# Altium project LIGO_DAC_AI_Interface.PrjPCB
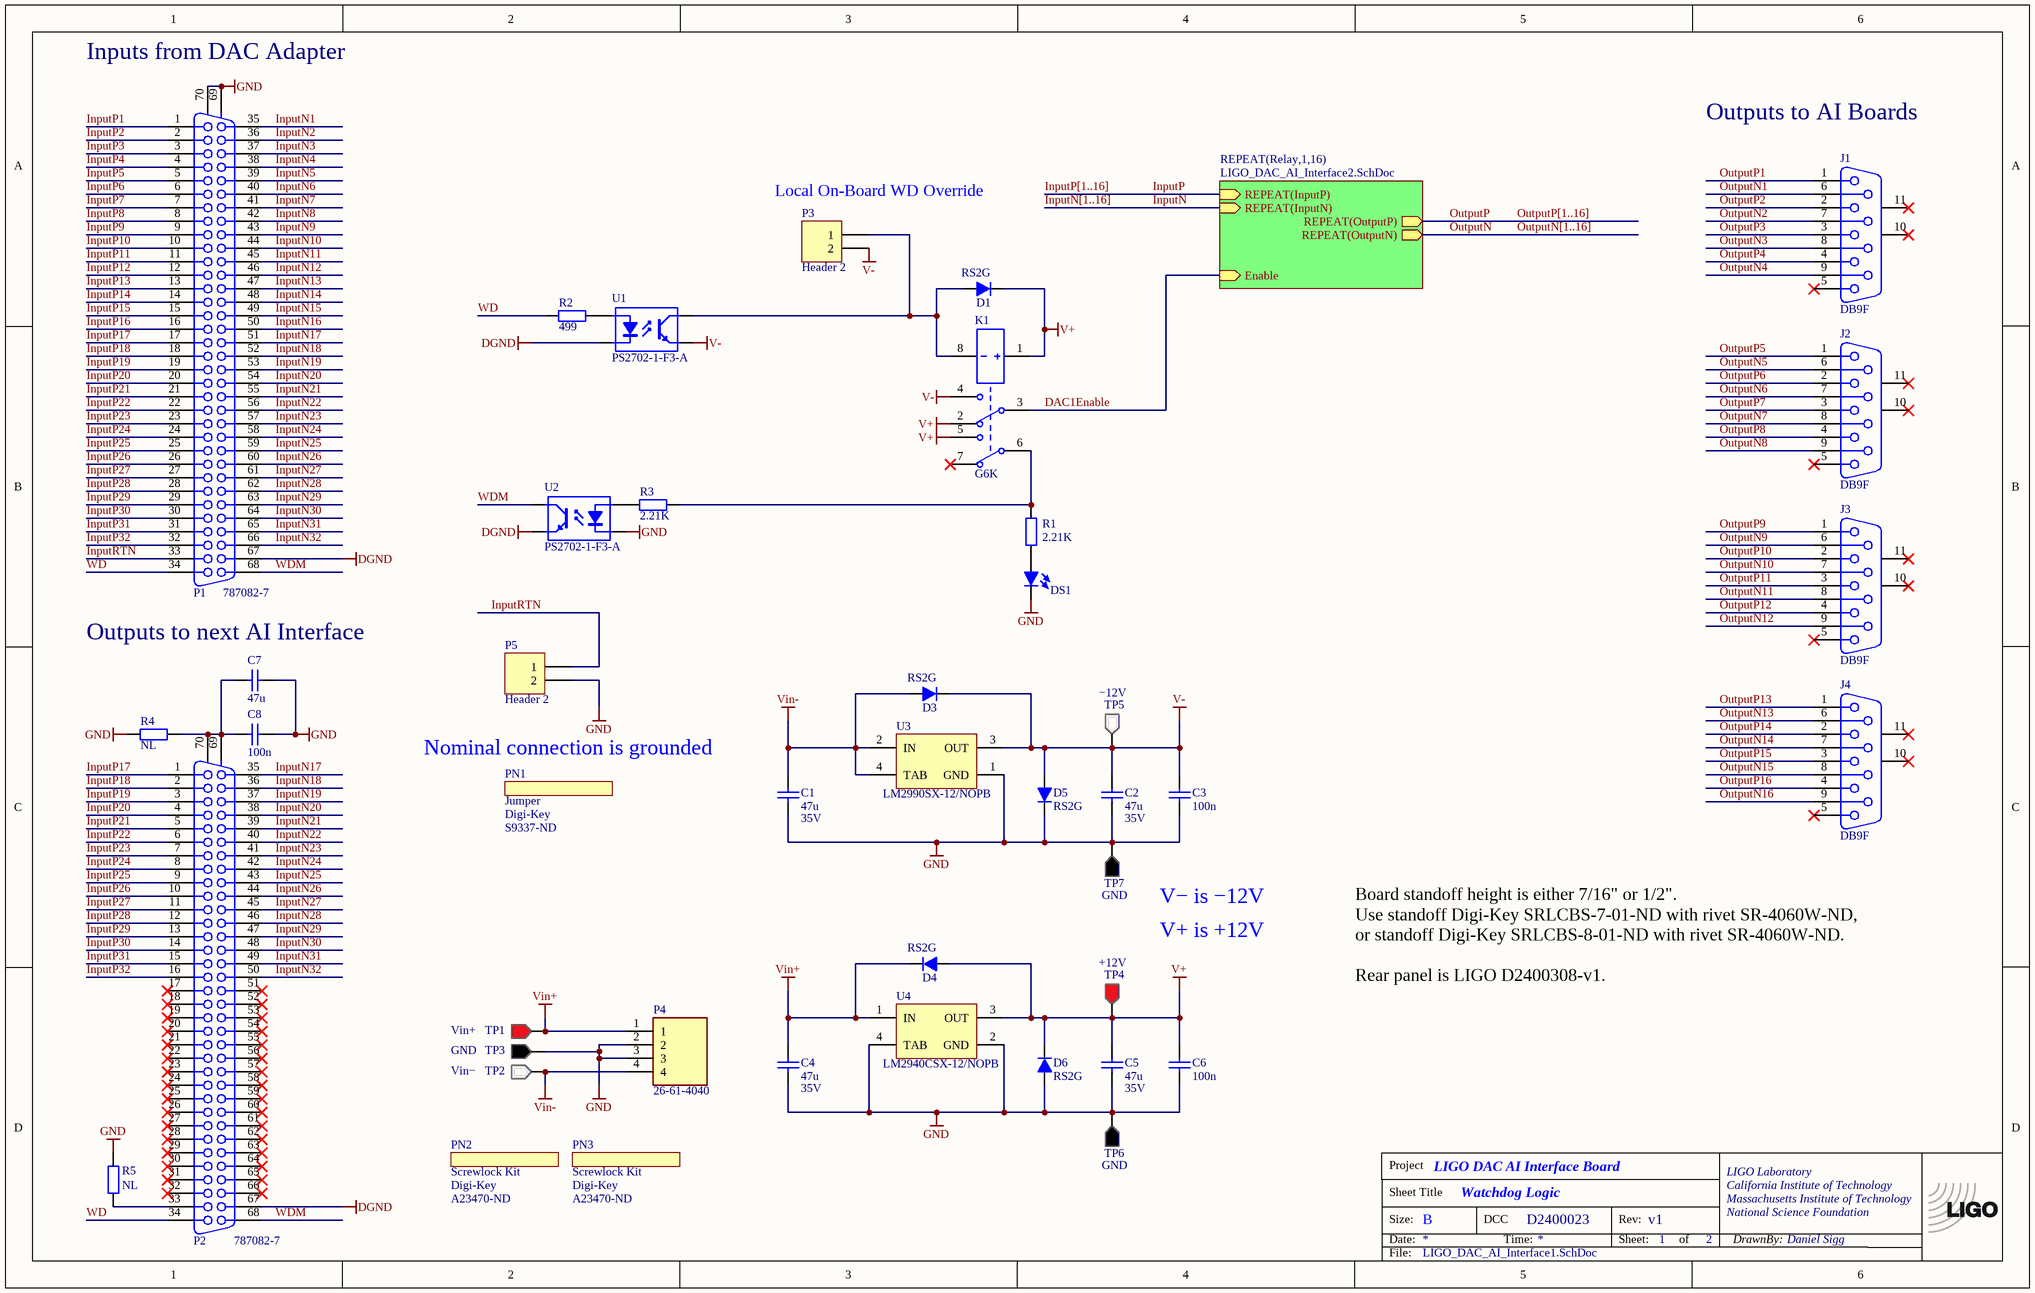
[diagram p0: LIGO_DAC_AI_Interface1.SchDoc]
Rev: v1; Project: LIGO DAC AI Interface Board; Eng: Daniel Sigg; DCC: D2400023
2 sheets, 92 parts. Net scope: hierarchical (ports join the sheet entries above them; power ports are global).
Board file: LIGO_DAC_AI_Interface.PcbDoc
Sheets:
  LIGO_DAC_AI_Interface1.SchDoc
    Relay1 = LIGO_DAC_AI_Interface2.SchDoc
    Relay2 = LIGO_DAC_AI_Interface2.SchDoc
    Relay3 = LIGO_DAC_AI_Interface2.SchDoc
    Relay4 = LIGO_DAC_AI_Interface2.SchDoc
    Relay5 = LIGO_DAC_AI_Interface2.SchDoc
    Relay6 = LIGO_DAC_AI_Interface2.SchDoc
    Relay7 = LIGO_DAC_AI_Interface2.SchDoc
    Relay8 = LIGO_DAC_AI_Interface2.SchDoc
    Relay9 = LIGO_DAC_AI_Interface2.SchDoc
    Relay10 = LIGO_DAC_AI_Interface2.SchDoc
    Relay11 = LIGO_DAC_AI_Interface2.SchDoc
    Relay12 = LIGO_DAC_AI_Interface2.SchDoc
    Relay13 = LIGO_DAC_AI_Interface2.SchDoc
    Relay14 = LIGO_DAC_AI_Interface2.SchDoc
    Relay15 = LIGO_DAC_AI_Interface2.SchDoc
    Relay16 = LIGO_DAC_AI_Interface2.SchDoc

## Sheet LIGO_DAC_AI_Interface1.SchDoc: Watchdog Logic
size B; Engineer: Daniel Sigg; DocumentNumber: D2400023; Revision: v1; SheetNumber: 1; SheetTotal: 2; PageSetup: Record=PageOptions¦CenterHorizontal=True¦CenterVertical=True¦PrintScale=1.12¦XCorrection=1.00¦YCorrection=1.00¦PrintKind=0¦BorderSize=5000000¦LeftOffset=0¦BottomOffset=0¦Orientation=2¦PaperLength=1000¦PaperWidth=1000¦Scale=100¦PaperSource=15¦PrintQuality=600¦MediaType=1¦DitherType=10¦PaperKind=Tabloid¦PrintScaleMode=1; SHEETSIZE: B

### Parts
*?  TitleBlock  (value not drawn)  (graphical)
C1  Voltage Rating: 35V  [CC5650-2220]  (hidden comment: 47u)
C2  Voltage Rating: 35V  [CC5650-2220]  (hidden comment: 47u)
C3  100n  [CC2013-0805]
C4  Voltage Rating: 35V  [CC5650-2220]  (hidden comment: 47u)
C5  Voltage Rating: 35V  [CC5650-2220]  (hidden comment: 47u)
C6  100n  [CC2013-0805]
C7  47u  [CC5650-2220]
C8  100n  [CC2013-0805]
D1  RS2G  [DO-SMB]
D3  RS2G  [DO-SMB]
D4  RS2G  [DO-SMB]
D5  RS2G  [DO-SMB]
D6  RS2G  [DO-SMB]
DS1  LED  [LED-1]  (value not drawn)
J1  DB9F  [DB9F-ST]
J2  DB9F  [DB9F-ST]
J3  DB9F  [DB9F-ST]
J4  DB9F  [DB9F-ST]
K1  G6K  [RELAY_G6K-2F]
P1  787082-7  [787082-7]
P2  787082-7  [787082-7]
P3  Header 2  [TSW-102-XX-YY-S]
P4  26-61-4040  [HDRV4W155P0X396_1X4_1570X1001X1536P]
P5  Header 2  [TSW-102-XX-YY-S]
PN1  Jumper  Part Number: S9337-ND  Distributor: Digi-Key  (mechanical)
PN2  Screwlock Kit  Part Number: A23470-ND  Distributor: Digi-Key  (mechanical)
PN3  Screwlock Kit  Part Number: A23470-ND  Distributor: Digi-Key  (mechanical)
R1  2.21K  [CR2012-0805]
R2  499  [CR2012-0805]
R3  2.21K  [CR2012-0805]
R4  NL  [CR2012-0805]
R5  NL  [CR2012-0805]
TP1  Vin+  [TP1-RED]
TP2  Vin−  [TP1-WHT]
TP3  GND  [TP1-BLK]
TP4  +12V  [TP1-RED]
TP5  −12V  [TP1-WHT]
TP6  GND  [TP1-BLK]
TP7  GND  [TP1-BLK]
U1  PS2702-1-F3-A  [PS2701A-1]
U2  PS2702-1-F3-A  [PS2701A-1]
U3  LM2990SX-12/NOPB  [KTT0003B_N]
U4  LM2940CSX-12/NOPB  [KTT0003B_N]

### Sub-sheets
REPEAT(Relay,1,16) = LIGO_DAC_AI_Interface2.SchDoc: REPEAT(InputP) (in), REPEAT(InputN) (in), REPEAT(OutputP) (out), REPEAT(OutputN) (out), Enable (in)

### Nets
DGND: P1.67 P2.67 U1.2(K) U2.3(E)
GND: C1.1 C2.1 C3.1 C4.1 C5.1 C6.1 C7.1 C8.1 D5.2(K) D6.1(A) DS1.1(K) P1.69(MH1) P1.70(MH2) P4.2 P4.3 P5.2 R4.2 R5.2 TP3.1 TP6.1 TP7.1 U2.2(K) U3.1(GND) U4.2(GND) U4.4(TAB)
V+: C5.2 C6.2 D1.2(K) D4.1(A) D6.2(K) K1.1(COIL1) K1.2(2NC) K1.5(1NO) TP4.1 U4.3(OUT)
V-: C2.2 C3.2 D3.2(K) D5.1(A) K1.4(2NO) P3.2 TP5.1 U1.3(E) U3.3(OUT)
Vin+: C4.2 D4.2(K) P4.1 TP1.1 U4.1(IN)
Vin-: C1.2 D3.1(A) P4.4 TP2.1 U3.2(IN) U3.4(TAB)
DAC1Enable: K1.3(2COM) ; sheet REPEAT(Relay,1,16)/Enable
InputN1: P1.35
InputN2: P1.36
InputN3: P1.37
InputN4: P1.38
InputN5: P1.39
InputN6: P1.40
InputN7: P1.41
InputN8: P1.42
InputN9: P1.43
InputN10: P1.44
InputN11: P1.45
InputN12: P1.46
InputN13: P1.47
InputN14: P1.48
InputN15: P1.49
InputN16: P1.50
InputN17: P1.51 P2.35
InputN18: P1.52 P2.36
InputN19: P1.53 P2.37
InputN20: P1.54 P2.38
InputN21: P1.55 P2.39
InputN22: P1.56 P2.40
InputN23: P1.57 P2.41
InputN24: P1.58 P2.42
InputN25: P1.59 P2.43
InputN26: P1.60 P2.44
InputN27: P1.61 P2.45
InputN28: P1.62 P2.46
InputN29: P1.63 P2.47
InputN30: P1.64 P2.48
InputN31: P1.65 P2.49
InputN32: P1.66 P2.50
InputP1: P1.1
InputP2: P1.2
InputP3: P1.3
InputP4: P1.4
InputP5: P1.5
InputP6: P1.6
InputP7: P1.7
InputP8: P1.8
InputP9: P1.9
InputP10: P1.10
InputP11: P1.11
InputP12: P1.12
InputP13: P1.13
InputP14: P1.14
InputP15: P1.15
InputP16: P1.16
InputP17: P1.17 P2.1
InputP18: P1.18 P2.2
InputP19: P1.19 P2.3
InputP20: P1.20 P2.4
InputP21: P1.21 P2.5
InputP22: P1.22 P2.6
InputP23: P1.23 P2.7
InputP24: P1.24 P2.8
InputP25: P1.25 P2.9
InputP26: P1.26 P2.10
InputP27: P1.27 P2.11
InputP28: P1.28 P2.12
InputP29: P1.29 P2.13
InputP30: P1.30 P2.14
InputP31: P1.31 P2.15
InputP32: P1.32 P2.16
InputRTN: P1.33 P5.1
OutputN1: J1.6
OutputN2: J1.7
OutputN3: J1.8
OutputN4: J1.9
OutputN5: J2.6
OutputN6: J2.7
OutputN7: J2.8
OutputN8: J2.9
OutputN9: J3.6
OutputN10: J3.7
OutputN11: J3.8
OutputN12: J3.9
OutputN13: J4.6
OutputN14: J4.7
OutputN15: J4.8
OutputN16: J4.9
OutputP1: J1.1
OutputP2: J1.2
OutputP3: J1.3
OutputP4: J1.4
OutputP5: J2.1
OutputP6: J2.2
OutputP7: J2.3
OutputP8: J2.4
OutputP9: J3.1
OutputP10: J3.2
OutputP11: J3.3
OutputP12: J3.4
OutputP13: J4.1
OutputP14: J4.2
OutputP15: J4.3
OutputP16: J4.4
WD: P1.34 P2.34 R2.1
WDM: P1.68 P2.68 U2.4(C)
NetC7_2: C7.2 C8.2 P2.69(MH1) P2.70(MH2) R4.1
NetD1_1: D1.1(A) K1.8(COIL2) P3.1 U1.4(C)
NetDS1_2: DS1.2(A) R1.1
NetK1_6: K1.6(1COM) R1.2 R3.2
NetP2_33: P2.33 R5.1
NetR2_2: R2.2 U1.1(A)
NetR3_1: R3.1 U2.1(A)

Not connected (* = marked no-connect by the designer): J1 5* 10(MH1)* 11(MH2)*; J2 5* 10(MH1)* 11(MH2)*; J3 5* 10(MH1)* 11(MH2)*; J4 5* 10(MH1)* 11(MH2)*; K1 7(1NC)*; P2 17* 18* 19* 20* 21* 22* 23* 24* 25* 26* 27* 28* 29* 30* 31* 32* 51* 52* 53* 54* 55* 56* 57* 58* 59* 60* 61* 62* 63* 64* 65* 66*

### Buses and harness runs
bus InputN[1..16]
bus InputP[1..16]
bus OutputN[1..16]
bus OutputP[1..16]

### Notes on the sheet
- (near P1) Inputs from DAC Adapter
- Outputs to AI Boards
- (near P3) Local On-Board WD Override
- Outputs to next AI Interface
- (near PN1) Nominal connection is grounded
- V− is −12V
- V+ is +12V
- Board standoff height is either 7/16" or 1/2".
  Use standoff Digi-Key SRLCBS-7-01-ND with rivet SR-4060W-ND,
  or standoff Digi-Key SRLCBS-8-01-ND with rivet SR-4060W-ND.
  Rear panel is LIGO D2400308-v1.

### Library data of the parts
C1 C2 C4 C5 = ChipCap: Capacitor, surface mount; Part Number: 445-C5750X7R1V476M230KCCT-ND; Tolerance: 10%
C3 C6 C8 = ChipCap: Capacitor, surface mount; Part Number: 311-1140-1-ND; Tolerance: 10%
C7 = ChipCap: Capacitor, surface mount; Part Number: 445-C5750X7R1V476M230KCCT-ND; Tolerance: 10%; Voltage Rating: 35V
D1 D3-D6 = DIODE: Single diode; Part Number: RS2G-E3/52TGICT-ND; Voltage Rating: 400V
DS1 = LED: Panel mount LED; Part Number: 67-1304-ND
J1-J4 = DB9F: Receptacle Assembly, 9 Position, Right Angle, .318 Series; Part Number: A34072-ND
K1 = Relay_DPDT_GK: Dual-pole dual-throw relay; Part Number: Z114CT-ND; Coil Voltage: 24V; Current Rating: 2A
P1 P2 = 787082-7: Receptacle Assembly, Shielded, Right Angle, AMPLIMITE; Part Number: A31814-ND
P3 P5 = Header 2: Header, 2-Pin; Part Number: SAM10844-ND
P4 = 26-61-4040: Connector; Manufacturer_Name: Molex; Part Number: WM5226-ND
PN1 = Partlist
PN2 PN3 = Partlist: Jackscrew Socket, Slotted For AMPLIMITE Series: 786585-2
R1 R3 = ChipRes1: Resistor, surface mount; Part Number: 311-2.21KCRCT-ND; Tolerance: 1%
R2 = ChipRes1: Resistor, surface mount; Part Number: 311-499CRCT-ND; Tolerance: 1%
R4 R5 = ChipRes1: Resistor, surface mount; Tolerance: 1%
TP1 TP4 = TP_POSITIVE: Testpoint, red; Part Number: 5005K-ND
TP2 TP5 = TP_NEGATIVE: Testpoint, white; Part Number: 5007K-ND
TP3 TP6 TP7 = TP_GND: Testpoint, black; Part Number: 5006K-ND
U1 U2 = PS2701A: High Isolation Voltage SOP Photocoupler; Part Number: 559-1027-1-ND
U3 = LM2990SX-12: Negative Low Dropout Regulator, 3-pin TO-263; Part Number: LM2990SX-12/NOPBCT-ND
U4 = LM2940CS-12/NOPB: 1A Low Dropout Regulator, 3-pin TO-263, Pb-Free; Part Number: LM2940CSX-12/NOPBCT-ND

## Sheet LIGO_DAC_AI_Interface2.SchDoc: Signal Relays
size A; Engineer: Daniel Sigg; DocumentNumber: D2400023; Revision: v1; SheetNumber: 2; SheetTotal: 2; SHEETSIZE: A
Used 16 times, as channels Relay1, Relay2, Relay3, Relay4, Relay5, Relay6, Relay7, Relay8, Relay9, Relay10, Relay11, Relay12, Relay13, Relay14, Relay15, Relay16. Parts and nets are listed once, with the designators drawn on the sheet.
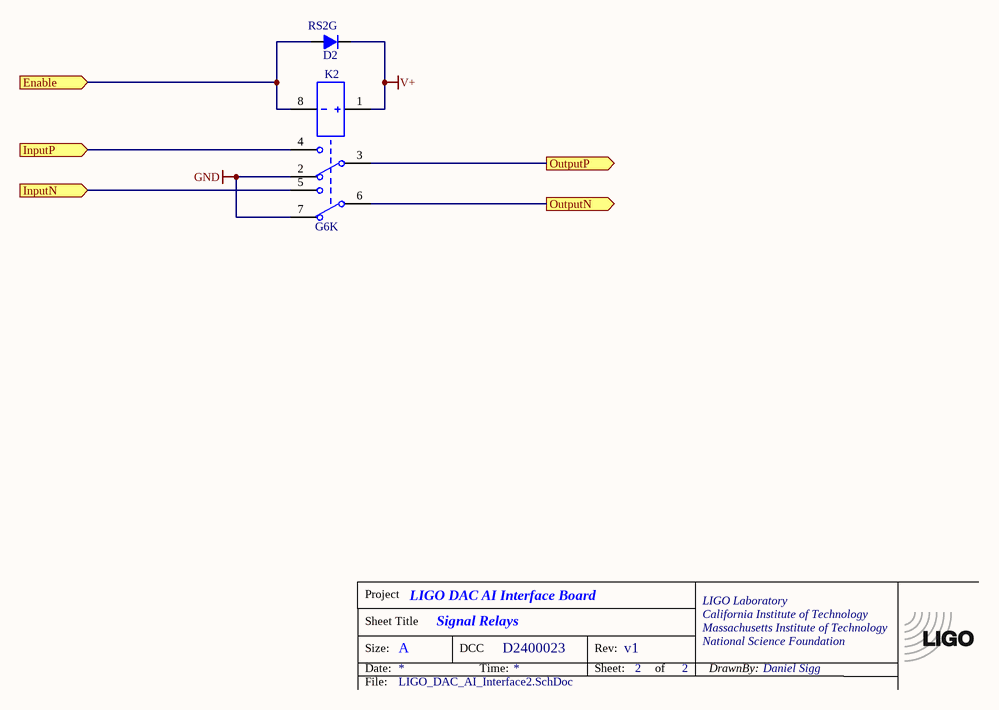
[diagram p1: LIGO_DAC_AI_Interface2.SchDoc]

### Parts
*?  TitleBlock  (value not drawn)  (graphical)
D2  RS2G  [DO-SMB]
K2  G6K  [RELAY_G6K-2F]

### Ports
Enable (in), InputN (in), InputP (in), OutputN (out), OutputP (out)

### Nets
GND: K2.2(2NC) K2.7(1NC)
V+: D2.2(K) K2.1(COIL1)
Enable: D2.1(A) K2.8(COIL2) ; port Enable
InputN: K2.5(1NO) ; port InputN
InputP: K2.4(2NO) ; port InputP
OutputN: K2.6(1COM) ; port OutputN
OutputP: K2.3(2COM) ; port OutputP

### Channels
Relay1: designators end in A; ports Enable=DAC1Enable InputN=InputN1 InputP=InputP1 OutputN=OutputN1 OutputP=OutputP1
Relay2: designators end in B; ports Enable=DAC1Enable InputN=InputN2 InputP=InputP2 OutputN=OutputN2 OutputP=OutputP2
Relay3: designators end in C; ports Enable=DAC1Enable InputN=InputN3 InputP=InputP3 OutputN=OutputN3 OutputP=OutputP3
Relay4: designators end in D; ports Enable=DAC1Enable InputN=InputN4 InputP=InputP4 OutputN=OutputN4 OutputP=OutputP4
Relay5: designators end in E; ports Enable=DAC1Enable InputN=InputN5 InputP=InputP5 OutputN=OutputN5 OutputP=OutputP5
Relay6: designators end in F; ports Enable=DAC1Enable InputN=InputN6 InputP=InputP6 OutputN=OutputN6 OutputP=OutputP6
Relay7: designators end in G; ports Enable=DAC1Enable InputN=InputN7 InputP=InputP7 OutputN=OutputN7 OutputP=OutputP7
Relay8: designators end in H; ports Enable=DAC1Enable InputN=InputN8 InputP=InputP8 OutputN=OutputN8 OutputP=OutputP8
Relay9: designators end in I; ports Enable=DAC1Enable InputN=InputN9 InputP=InputP9 OutputN=OutputN9 OutputP=OutputP9
Relay10: designators end in J; ports Enable=DAC1Enable InputN=InputN10 InputP=InputP10 OutputN=OutputN10 OutputP=OutputP10
Relay11: designators end in K; ports Enable=DAC1Enable InputN=InputN11 InputP=InputP11 OutputN=OutputN11 OutputP=OutputP11
Relay12: designators end in L; ports Enable=DAC1Enable InputN=InputN12 InputP=InputP12 OutputN=OutputN12 OutputP=OutputP12
Relay13: designators end in M; ports Enable=DAC1Enable InputN=InputN13 InputP=InputP13 OutputN=OutputN13 OutputP=OutputP13
Relay14: designators end in N; ports Enable=DAC1Enable InputN=InputN14 InputP=InputP14 OutputN=OutputN14 OutputP=OutputP14
Relay15: designators end in O; ports Enable=DAC1Enable InputN=InputN15 InputP=InputP15 OutputN=OutputN15 OutputP=OutputP15
Relay16: designators end in P; ports Enable=DAC1Enable InputN=InputN16 InputP=InputP16 OutputN=OutputN16 OutputP=OutputP16

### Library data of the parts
D2 = DIODE: as D1 on sheet LIGO_DAC_AI_Interface1
K2 = Relay_DPDT_GK: as K1 on sheet LIGO_DAC_AI_Interface1

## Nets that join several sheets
GND: LIGO_DAC_AI_Interface1 (25 pins), Relay1 (K2A.2 K2A.7), Relay2 (K2B.2 K2B.7), Relay3 (K2C.2 K2C.7), Relay4 (K2D.2 K2D.7), Relay5 (K2E.2 K2E.7), Relay6 (K2F.2 K2F.7), Relay7 (K2G.2 K2G.7), Relay8 (K2H.2 K2H.7), Relay9 (K2I.2 K2I.7), Relay10 (K2J.2 K2J.7), Relay11 (K2K.2 K2K.7), Relay12 (K2L.2 K2L.7), Relay13 (K2M.2 K2M.7), Relay14 (K2N.2 K2N.7), Relay15 (K2O.2 K2O.7), Relay16 (K2P.2 K2P.7)
V+: LIGO_DAC_AI_Interface1 (10 pins), Relay1 (D2A.2 K2A.1), Relay2 (D2B.2 K2B.1), Relay3 (D2C.2 K2C.1), Relay4 (D2D.2 K2D.1), Relay5 (D2E.2 K2E.1), Relay6 (D2F.2 K2F.1), Relay7 (D2G.2 K2G.1), Relay8 (D2H.2 K2H.1), Relay9 (D2I.2 K2I.1), Relay10 (D2J.2 K2J.1), Relay11 (D2K.2 K2K.1), Relay12 (D2L.2 K2L.1), Relay13 (D2M.2 K2M.1), Relay14 (D2N.2 K2N.1), Relay15 (D2O.2 K2O.1), Relay16 (D2P.2 K2P.1)
DAC1Enable: LIGO_DAC_AI_Interface1 (K1.3), Relay1 (D2A.1 K2A.8), Relay2 (D2B.1 K2B.8), Relay3 (D2C.1 K2C.8), Relay4 (D2D.1 K2D.8), Relay5 (D2E.1 K2E.8), Relay6 (D2F.1 K2F.8), Relay7 (D2G.1 K2G.8), Relay8 (D2H.1 K2H.8), Relay9 (D2I.1 K2I.8), Relay10 (D2J.1 K2J.8), Relay11 (D2K.1 K2K.8), Relay12 (D2L.1 K2L.8), Relay13 (D2M.1 K2M.8), Relay14 (D2N.1 K2N.8), Relay15 (D2O.1 K2O.8), Relay16 (D2P.1 K2P.8)
InputN1: LIGO_DAC_AI_Interface1 (P1.35), Relay1 (K2A.5)
InputN2: LIGO_DAC_AI_Interface1 (P1.36), Relay2 (K2B.5)
InputN3: LIGO_DAC_AI_Interface1 (P1.37), Relay3 (K2C.5)
InputN4: LIGO_DAC_AI_Interface1 (P1.38), Relay4 (K2D.5)
InputN5: LIGO_DAC_AI_Interface1 (P1.39), Relay5 (K2E.5)
InputN6: LIGO_DAC_AI_Interface1 (P1.40), Relay6 (K2F.5)
InputN7: LIGO_DAC_AI_Interface1 (P1.41), Relay7 (K2G.5)
InputN8: LIGO_DAC_AI_Interface1 (P1.42), Relay8 (K2H.5)
InputN9: LIGO_DAC_AI_Interface1 (P1.43), Relay9 (K2I.5)
InputN10: LIGO_DAC_AI_Interface1 (P1.44), Relay10 (K2J.5)
InputN11: LIGO_DAC_AI_Interface1 (P1.45), Relay11 (K2K.5)
InputN12: LIGO_DAC_AI_Interface1 (P1.46), Relay12 (K2L.5)
InputN13: LIGO_DAC_AI_Interface1 (P1.47), Relay13 (K2M.5)
InputN14: LIGO_DAC_AI_Interface1 (P1.48), Relay14 (K2N.5)
InputN15: LIGO_DAC_AI_Interface1 (P1.49), Relay15 (K2O.5)
InputN16: LIGO_DAC_AI_Interface1 (P1.50), Relay16 (K2P.5)
InputP1: LIGO_DAC_AI_Interface1 (P1.1), Relay1 (K2A.4)
InputP2: LIGO_DAC_AI_Interface1 (P1.2), Relay2 (K2B.4)
InputP3: LIGO_DAC_AI_Interface1 (P1.3), Relay3 (K2C.4)
InputP4: LIGO_DAC_AI_Interface1 (P1.4), Relay4 (K2D.4)
InputP5: LIGO_DAC_AI_Interface1 (P1.5), Relay5 (K2E.4)
InputP6: LIGO_DAC_AI_Interface1 (P1.6), Relay6 (K2F.4)
InputP7: LIGO_DAC_AI_Interface1 (P1.7), Relay7 (K2G.4)
InputP8: LIGO_DAC_AI_Interface1 (P1.8), Relay8 (K2H.4)
InputP9: LIGO_DAC_AI_Interface1 (P1.9), Relay9 (K2I.4)
InputP10: LIGO_DAC_AI_Interface1 (P1.10), Relay10 (K2J.4)
InputP11: LIGO_DAC_AI_Interface1 (P1.11), Relay11 (K2K.4)
InputP12: LIGO_DAC_AI_Interface1 (P1.12), Relay12 (K2L.4)
InputP13: LIGO_DAC_AI_Interface1 (P1.13), Relay13 (K2M.4)
InputP14: LIGO_DAC_AI_Interface1 (P1.14), Relay14 (K2N.4)
InputP15: LIGO_DAC_AI_Interface1 (P1.15), Relay15 (K2O.4)
InputP16: LIGO_DAC_AI_Interface1 (P1.16), Relay16 (K2P.4)
OutputN1: LIGO_DAC_AI_Interface1 (J1.6), Relay1 (K2A.6)
OutputN2: LIGO_DAC_AI_Interface1 (J1.7), Relay2 (K2B.6)
OutputN3: LIGO_DAC_AI_Interface1 (J1.8), Relay3 (K2C.6)
OutputN4: LIGO_DAC_AI_Interface1 (J1.9), Relay4 (K2D.6)
OutputN5: LIGO_DAC_AI_Interface1 (J2.6), Relay5 (K2E.6)
OutputN6: LIGO_DAC_AI_Interface1 (J2.7), Relay6 (K2F.6)
OutputN7: LIGO_DAC_AI_Interface1 (J2.8), Relay7 (K2G.6)
OutputN8: LIGO_DAC_AI_Interface1 (J2.9), Relay8 (K2H.6)
OutputN9: LIGO_DAC_AI_Interface1 (J3.6), Relay9 (K2I.6)
OutputN10: LIGO_DAC_AI_Interface1 (J3.7), Relay10 (K2J.6)
OutputN11: LIGO_DAC_AI_Interface1 (J3.8), Relay11 (K2K.6)
OutputN12: LIGO_DAC_AI_Interface1 (J3.9), Relay12 (K2L.6)
OutputN13: LIGO_DAC_AI_Interface1 (J4.6), Relay13 (K2M.6)
OutputN14: LIGO_DAC_AI_Interface1 (J4.7), Relay14 (K2N.6)
OutputN15: LIGO_DAC_AI_Interface1 (J4.8), Relay15 (K2O.6)
OutputN16: LIGO_DAC_AI_Interface1 (J4.9), Relay16 (K2P.6)
OutputP1: LIGO_DAC_AI_Interface1 (J1.1), Relay1 (K2A.3)
OutputP2: LIGO_DAC_AI_Interface1 (J1.2), Relay2 (K2B.3)
OutputP3: LIGO_DAC_AI_Interface1 (J1.3), Relay3 (K2C.3)
OutputP4: LIGO_DAC_AI_Interface1 (J1.4), Relay4 (K2D.3)
OutputP5: LIGO_DAC_AI_Interface1 (J2.1), Relay5 (K2E.3)
OutputP6: LIGO_DAC_AI_Interface1 (J2.2), Relay6 (K2F.3)
OutputP7: LIGO_DAC_AI_Interface1 (J2.3), Relay7 (K2G.3)
OutputP8: LIGO_DAC_AI_Interface1 (J2.4), Relay8 (K2H.3)
OutputP9: LIGO_DAC_AI_Interface1 (J3.1), Relay9 (K2I.3)
OutputP10: LIGO_DAC_AI_Interface1 (J3.2), Relay10 (K2J.3)
OutputP11: LIGO_DAC_AI_Interface1 (J3.3), Relay11 (K2K.3)
OutputP12: LIGO_DAC_AI_Interface1 (J3.4), Relay12 (K2L.3)
OutputP13: LIGO_DAC_AI_Interface1 (J4.1), Relay13 (K2M.3)
OutputP14: LIGO_DAC_AI_Interface1 (J4.2), Relay14 (K2N.3)
OutputP15: LIGO_DAC_AI_Interface1 (J4.3), Relay15 (K2O.3)
OutputP16: LIGO_DAC_AI_Interface1 (J4.4), Relay16 (K2P.3)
